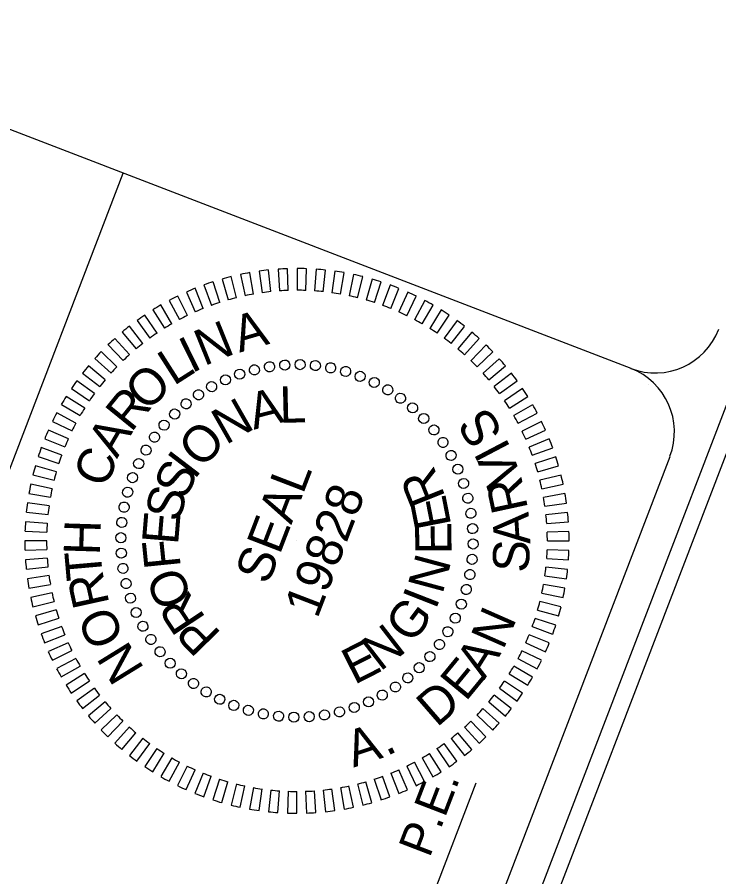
# Model space of a CAD drawing. Extents: x 1015221 to 1064345, y 619216 to 647967.
# Drawn here: x 1026680 to 1027505, y 642855 to 643866 of the extents above; entities that cross this region are included whole.
import ezdxf

# ---------------------------------------------------------------- set-up
doc = ezdxf.new("R2010")
doc.units = 0
for name, color, linetype in [('Scratch_Level_0', 7, 'Continuous'), ('Sheet PE Seal Cell', 7, 'Continuous'), ('Sheet Plot Border Inside CELL', 7, 'Continuous'), ('Sheet Title CELL', 7, 'Continuous')]:
    doc.layers.add(name, color=color, linetype=linetype)

msp = doc.modelspace()

# ---------------------------------------------------------------- linework, layer by layer
at = {"layer": 'Scratch_Level_0'}
for p, q in [((1027422.6, 643434.5), (1027422.6, 643434.5)), ((1027008.9, 643250.4), (1027008.9, 643250.4))]:
    msp.add_line(p, q, dxfattribs=at)
at = {"layer": 'Sheet PE Seal Cell'}
for p, q in [((1026964.4, 643567.5), (1026968, 643542.1)), ((1026978.2, 643543.4), (1026975.5, 643568.8)), ((1026986.7, 643569.8), (1026988.4, 643544.3)), ((1026998.7, 643544.8), (1026997.8, 643570.4)), ((1027009, 643570.6), (1027009, 643545)), ((1027019.3, 643544.8), (1027020.2, 643570.4)), ((1027031.3, 643569.8), (1027029.5, 643544.2)), ((1027039.8, 643543.3), (1027042.5, 643568.8)), ((1027053.6, 643567.4), (1027050, 643542.1)), ((1026920.7, 643558.2), (1026927.8, 643533.6)), ((1026937.7, 643536.2), (1026931.5, 643561.1)), ((1026942.4, 643563.6), (1026947.8, 643538.5)), ((1026957.8, 643540.5), (1026953.4, 643565.7)), ((1027060.1, 643540.5), (1027064.6, 643565.7)), ((1027075.6, 643563.6), (1027070.2, 643538.5)), ((1027080.3, 643536.2), (1027086.5, 643561)), ((1027097.2, 643558.1), (1027090.2, 643533.5)), ((1026898.6, 643523.5), (1026889.1, 643547.3)), ((1026899.5, 643551.3), (1026908.2, 643527.2)), ((1026918, 643530.6), (1026910.1, 643554.9)), ((1027100, 643530.5), (1027107.9, 643554.9)), ((1027118.5, 643551.2), (1027109.7, 643527.2)), ((1027119.3, 643523.5), (1027128.9, 643547.2)), ((1026879.9, 643515.2), (1026868.6, 643538.2)), ((1026878.8, 643542.9), (1026889.2, 643519.5)), ((1027139.2, 643542.9), (1027128.8, 643519.5)), ((1027138.1, 643515.1), (1027149.3, 643538.1)), ((1026861.7, 643505.5), (1026848.9, 643527.7)), ((1026858.7, 643533.1), (1026870.7, 643510.5)), ((1027159.3, 643533.1), (1027147.3, 643510.4)), ((1027156.3, 643505.5), (1027169.1, 643527.6)), ((1026839.3, 643522), (1026852.9, 643500.3)), ((1027178.7, 643521.9), (1027165.1, 643500.2)), ((1026820.8, 643509.5), (1026835.8, 643488.8)), ((1026844.3, 643494.7), (1026829.9, 643515.9)), ((1027173.7, 643494.6), (1027188, 643515.8)), ((1027197.2, 643509.4), (1027182.1, 643488.7)), ((1026827.6, 643482.6), (1026811.9, 643502.8)), ((1027190.3, 643482.5), (1027206.1, 643502.6)), ((1026811.9, 643469.4), (1026794.7, 643488.4)), ((1026803.2, 643495.7), (1026819.6, 643476.1)), ((1027214.8, 643495.6), (1027198.3, 643476)), ((1027206.1, 643469.2), (1027223.2, 643488.3)), ((1026786.6, 643480.8), (1026804.4, 643462.4)), ((1027231.4, 643480.7), (1027213.6, 643462.2)), ((1026797.1, 643455.1), (1026778.7, 643472.9)), ((1027220.9, 643455), (1027239.3, 643472.7)), ((1026783.3, 643439.8), (1026763.7, 643456.3)), ((1026771, 643464.7), (1026790.1, 643447.6)), ((1026976.6, 643455.4), (1026976.6, 643455.4)), ((1026994.6, 643457.3), (1026994.6, 643457.3)), ((1027012.5, 643457.9), (1027012.5, 643457.9)), ((1027030.6, 643456.7), (1027030.6, 643456.7)), ((1027246.9, 643464.6), (1027227.9, 643447.4)), ((1027234.6, 643439.7), (1027254.2, 643456.1)), ((1026756.7, 643447.6), (1026776.8, 643431.8)), ((1026941.4, 643446.7), (1026941.4, 643446.7)), ((1026958.7, 643451.6), (1026958.7, 643451.6)), ((1027048.6, 643453.8), (1027048.6, 643453.8)), ((1027066, 643449.7), (1027066, 643449.7)), ((1027261.3, 643447.4), (1027241.1, 643431.7)), ((1026770.7, 643423.6), (1026749.9, 643438.7)), ((1026924.6, 643439.9), (1026924.6, 643439.9)), ((1027083.3, 643444), (1027083.3, 643444)), ((1027100, 643436.7), (1027100, 643436.7)), ((1027247.3, 643423.5), (1027268, 643438.5)), ((1026743.5, 643429.5), (1026764.8, 643415.2)), ((1026908.3, 643432), (1026908.3, 643432)), ((1027115.7, 643428), (1027115.7, 643428)), ((1027274.4, 643429.4), (1027253.2, 643415)), ((1026759.2, 643406.6), (1026737.4, 643420.2)), ((1026893.1, 643422.4), (1026893.1, 643422.4)), ((1027130.9, 643418.2), (1027130.9, 643418.2)), ((1027258.8, 643406.4), (1027280.5, 643420)), ((1026731.7, 643410.6), (1026753.9, 643397.8)), ((1026878.3, 643411.7), (1026878.3, 643411.7)), ((1027145.2, 643406.9), (1027145.2, 643406.9)), ((1027286.2, 643410.4), (1027264, 643397.6)), ((1026748.9, 643388.8), (1026726.3, 643400.8)), ((1026864.9, 643399.6), (1026864.9, 643399.6)), ((1027269, 643388.6), (1027291.6, 643400.6)), ((1026721.2, 643390.8), (1026744.2, 643379.6)), ((1026852.4, 643386.7), (1026852.4, 643386.7)), ((1027158.1, 643394.5), (1027158.1, 643394.5)), ((1027296.7, 643390.7), (1027273.7, 643379.5)), ((1026739.9, 643370.3), (1026716.5, 643380.7)), ((1027170.2, 643381), (1027170.2, 643381)), ((1027278, 643370.1), (1027301.4, 643380.5)), ((1026712.1, 643370.4), (1026735.8, 643360.8)), ((1026841.1, 643372.4), (1026841.1, 643372.4)), ((1027180.9, 643366.2), (1027180.9, 643366.2)), ((1027305.8, 643370.3), (1027282, 643360.7)), ((1026732.1, 643351.2), (1026708.1, 643360)), ((1026831.3, 643357.2), (1026831.3, 643357.2)), ((1027285.7, 643351.1), (1027309.8, 643359.8)), ((1026704.4, 643349.4), (1026728.8, 643341.5)), ((1027190.5, 643351), (1027190.5, 643351)), ((1027313.4, 643349.3), (1027289.1, 643341.3)), ((1026725.8, 643331.7), (1026701.2, 643338.7)), ((1026822.6, 643341.5), (1026822.6, 643341.5)), ((1027198.4, 643334.7), (1027198.4, 643334.7)), ((1027292.1, 643331.5), (1027316.7, 643338.6)), ((1026698.3, 643328), (1026723.1, 643321.8)), ((1026815.3, 643324.8), (1026815.3, 643324.8)), ((1027319.6, 643327.8), (1027294.7, 643321.6)), ((1026720.8, 643311.7), (1026695.8, 643317.1)), ((1027205.2, 643317.9), (1027205.2, 643317.9)), ((1027297, 643311.6), (1027322.1, 643316.9)), ((1026693.6, 643306.1), (1026718.8, 643301.6)), ((1026809.6, 643307.5), (1026809.6, 643307.5)), ((1027324.2, 643305.9), (1027299, 643301.5)), ((1026717.2, 643291.5), (1026691.9, 643295.1)), ((1027210.1, 643300.6), (1027210.1, 643300.6)), ((1027300.6, 643291.3), (1027326, 643294.9)), ((1026690.5, 643284), (1026716, 643281.3)), ((1026805.5, 643290.1), (1026805.5, 643290.1)), ((1027327.3, 643283.8), (1027301.9, 643281.1)), ((1027213.9, 643282.8), (1027213.9, 643282.8)), ((1026715.1, 643271), (1026689.5, 643272.8)), ((1026802.6, 643272.1), (1026802.6, 643272.1)), ((1027215.8, 643264.7), (1027215.8, 643264.7)), ((1027302.8, 643270.9), (1027328.3, 643272.6)), ((1026688.9, 643261.7), (1026714.5, 643260.8)), ((1026801.4, 643254), (1026801.4, 643254)), ((1027328.9, 643261.5), (1027303.3, 643260.6)), ((1026714.4, 643250.5), (1026688.7, 643250.5)), ((1027216.4, 643246.8), (1027216.4, 643246.8)), ((1027303.5, 643250.3), (1027329.1, 643250.3)), ((1026688.9, 643239.3), (1026714.5, 643240.2)), ((1026802, 643236.1), (1026802, 643236.1)), ((1027328.9, 643239.1), (1027303.3, 643240)), ((1026715.1, 643229.9), (1026689.5, 643228.2)), ((1027215.2, 643228.7), (1027215.2, 643228.7)), ((1027302.7, 643229.8), (1027328.3, 643228)), ((1026690.5, 643217), (1026716, 643219.7)), ((1026804, 643218.1), (1026804, 643218.1)), ((1027327.3, 643216.8), (1027301.8, 643219.5)), ((1026717.2, 643209.5), (1026691.8, 643205.9)), ((1027212.3, 643210.8), (1027212.3, 643210.8)), ((1027300.6, 643209.3), (1027325.9, 643205.8)), ((1026693.6, 643194.9), (1026718.8, 643199.3)), ((1026807.7, 643200.2), (1026807.7, 643200.2)), ((1027208.2, 643193.3), (1027208.2, 643193.3)), ((1027324.2, 643194.7), (1027299, 643199.2)), ((1026720.8, 643189.3), (1026695.7, 643183.9)), ((1026812.6, 643182.9), (1026812.6, 643182.9)), ((1027297, 643189.1), (1027322.1, 643183.7)), ((1026698.2, 643173), (1026723.1, 643179.2)), ((1027202.5, 643176), (1027202.5, 643176)), ((1027319.5, 643172.9), (1027294.7, 643179.1)), ((1026725.7, 643169.3), (1026701.1, 643162.2)), ((1026819.4, 643166.1), (1026819.4, 643166.1)), ((1027292, 643169.1), (1027316.6, 643162.1)), ((1026704.4, 643151.6), (1026728.7, 643159.5)), ((1027195.2, 643159.4), (1027195.2, 643159.4)), ((1027313.4, 643151.4), (1027289, 643159.3)), ((1026732.1, 643149.7), (1026708, 643141)), ((1026827.3, 643149.8), (1026827.3, 643149.8)), ((1027186.5, 643143.7), (1027186.5, 643143.7)), ((1027285.7, 643149.6), (1027309.7, 643140.8)), ((1026712, 643130.6), (1026735.8, 643140.1)), ((1026836.9, 643134.6), (1026836.9, 643134.6)), ((1027305.7, 643130.4), (1027282, 643140)), ((1026739.8, 643130.7), (1026716.4, 643120.3)), ((1027176.7, 643128.4), (1027176.7, 643128.4)), ((1027278, 643130.5), (1027301.4, 643120.1)), ((1026721.1, 643110.1), (1026744.1, 643121.4)), ((1026748.8, 643112.2), (1026726.2, 643100.2)), ((1026847.7, 643119.8), (1026847.7, 643119.8)), ((1027165.4, 643114.1), (1027165.4, 643114.1)), ((1027268.9, 643112), (1027291.6, 643100)), ((1027296.6, 643110), (1027273.6, 643121.2)), ((1026731.6, 643090.4), (1026753.8, 643103.2)), ((1026859.7, 643106.4), (1026859.7, 643106.4)), ((1027286.1, 643090.2), (1027264, 643103.1)), ((1026759.1, 643094.4), (1026737.3, 643080.8)), ((1026872.6, 643093.9), (1026872.6, 643093.9)), ((1027153, 643101.2), (1027153, 643101.2)), ((1027258.7, 643094.2), (1027280.4, 643080.7)), ((1026743.4, 643071.5), (1026764.7, 643085.8)), ((1026886.9, 643082.6), (1026886.9, 643082.6)), ((1027139.5, 643089.2), (1027139.5, 643089.2)), ((1027274.3, 643071.3), (1027253.1, 643085.6)), ((1026770.6, 643077.3), (1026749.8, 643062.3)), ((1026902.2, 643072.8), (1026902.2, 643072.8)), ((1027124.7, 643078.4), (1027124.7, 643078.4)), ((1027247.2, 643077.2), (1027267.9, 643062.1)), ((1026756.6, 643053.4), (1026776.7, 643069.1)), ((1026917.9, 643064.1), (1026917.9, 643064.1)), ((1027109.5, 643068.8), (1027109.5, 643068.8)), ((1027261.1, 643053.2), (1027241, 643069)), ((1026783.2, 643061.1), (1026763.6, 643044.7)), ((1026770.9, 643036.2), (1026790, 643053.4)), ((1026934.5, 643056.8), (1026934.5, 643056.8)), ((1027076.4, 643054.1), (1027076.4, 643054.1)), ((1027093.2, 643060.9), (1027093.2, 643060.9)), ((1027246.8, 643036.1), (1027227.7, 643053.2)), ((1027234.5, 643061), (1027254.1, 643044.5)), ((1026797, 643045.9), (1026778.5, 643028.1)), ((1026951.8, 643051.1), (1026951.8, 643051.1)), ((1026969.3, 643047), (1026969.3, 643047)), ((1026987.2, 643044.1), (1026987.2, 643044.1)), ((1027005.3, 643042.9), (1027005.3, 643042.9)), ((1027023.2, 643043.5), (1027023.2, 643043.5)), ((1027041.3, 643045.5), (1027041.3, 643045.5)), ((1027059.1, 643049.2), (1027059.1, 643049.2)), ((1027220.7, 643045.7), (1027239.2, 643027.9)), ((1026786.4, 643020.2), (1026804.2, 643038.6)), ((1026811.7, 643031.6), (1026794.6, 643012.5)), ((1027205.9, 643031.5), (1027223.1, 643012.4)), ((1027231.2, 643020), (1027213.5, 643038.5)), ((1026803, 643005.2), (1026819.5, 643024.8)), ((1027214.6, 643005.1), (1027198.2, 643024.7)), ((1026827.5, 643018.3), (1026811.7, 642998.2)), ((1026820.6, 642991.4), (1026835.7, 643012.2)), ((1027197, 642991.3), (1027182, 643012.1)), ((1027190.2, 643018.2), (1027205.9, 642998.1)), ((1026844.1, 643006.3), (1026829.8, 642985)), ((1026839.2, 642978.9), (1026852.7, 643000.7)), ((1027173.5, 643006.2), (1027187.9, 642984.9)), ((1026861.6, 642995.4), (1026848.7, 642973.2)), ((1027156.1, 642995.3), (1027168.9, 642973.1)), ((1027178.5, 642978.8), (1027164.9, 643000.6)), ((1026858.5, 642967.8), (1026870.5, 642990.4)), ((1026879.7, 642985.7), (1026868.5, 642962.7)), ((1026878.6, 642958), (1026889, 642981.4)), ((1027139, 642957.9), (1027128.6, 642981.3)), ((1027138, 642985.6), (1027149.2, 642962.6)), ((1027159.1, 642967.7), (1027147.1, 642990.3)), ((1026898.5, 642977.3), (1026888.9, 642953.6)), ((1026899.3, 642949.6), (1026908.1, 642973.6)), ((1026917.8, 642970.3), (1026909.9, 642945.9)), ((1027118.3, 642949.5), (1027109.6, 642973.6)), ((1027119.2, 642977.3), (1027128.8, 642953.5)), ((1026920.6, 642942.7), (1026927.6, 642967.3)), ((1026937.6, 642964.6), (1026931.4, 642939.8)), ((1026942.2, 642937.3), (1026947.6, 642962.3)), ((1026957.7, 642960.3), (1026953.2, 642935.1)), ((1027060, 642960.3), (1027064.4, 642935.1)), ((1027075.4, 642937.2), (1027070.1, 642962.3)), ((1027080.1, 642964.6), (1027086.3, 642939.7)), ((1027097.1, 642942.6), (1027090, 642967.2)), ((1027099.8, 642970.2), (1027107.8, 642945.9)), ((1026964.3, 642933.4), (1026967.8, 642958.7)), ((1026978, 642957.5), (1026975.3, 642932)), ((1026986.5, 642931), (1026988.3, 642956.6)), ((1026998.5, 642956), (1026997.6, 642930.4)), ((1027008.8, 642930.2), (1027008.8, 642955.9)), ((1027019.1, 642956), (1027020, 642930.4)), ((1027031.1, 642931), (1027029.4, 642956.6)), ((1027039.6, 642957.5), (1027042.3, 642932)), ((1027053.4, 642933.3), (1027049.8, 642958.7))]:
    msp.add_line(p, q, dxfattribs=at)
for radius, start, end in [(320.2, 95.983, 97.983), (320.2, 91.983, 93.983), (320.2, 87.983, 89.983), (320.2, 83.983, 85.983), (320.2, 79.983, 81.983), (320.2, 103.983, 105.983), (320.2, 99.983, 101.983), (320.2, 75.983, 77.983), (320.2, 71.983, 73.983), (320.2, 111.983, 113.983), (320.2, 107.983, 109.983), (320.2, 67.983, 69.983), (320.2, 115.983, 117.983), (294.6, 103.983, 105.983), (294.6, 99.983, 101.983), (294.6, 95.983, 97.983), (294.6, 91.983, 93.983), (294.6, 87.983, 89.983), (294.6, 83.983, 85.983), (294.6, 79.983, 81.983), (294.6, 75.983, 77.983), (320.2, 63.983, 65.983), (320.2, 119.983, 121.983), (294.6, 107.983, 109.983), (294.6, 71.983, 73.983), (294.6, 67.983, 69.983), (320.2, 59.983, 61.983), (294.6, 111.983, 113.983), (294.6, 63.983, 65.983), (320.2, 55.983, 57.983), (320.2, 123.983, 125.983), (294.6, 115.983, 117.983), (294.6, 59.983, 61.983), (320.2, 51.983, 53.983), (320.2, 127.983, 129.983), (294.6, 119.983, 121.983), (294.6, 55.983, 57.983), (320.2, 131.983, 133.983), (294.6, 123.983, 125.983), (294.6, 51.983, 53.983), (320.2, 47.983, 49.983), (294.6, 127.983, 129.983), (294.6, 47.983, 49.983), (320.2, 43.983, 45.983), (320.2, 135.983, 137.983), (294.6, 131.983, 133.983), (320.2, 139.983, 141.983), (294.6, 43.983, 45.983), (320.2, 39.983, 41.983), (294.6, 135.983, 137.983), (294.6, 39.983, 41.983), (320.2, 35.983, 37.983), (320.2, 143.983, 145.983), (294.6, 139.983, 141.983), (294.6, 35.983, 37.983), (320.2, 31.983, 33.983), (320.2, 147.983, 149.983), (294.6, 143.983, 145.983), (294.6, 31.983, 33.983), (294.6, 147.983, 149.983), (320.2, 27.983, 29.983), (320.2, 151.983, 153.983), (294.6, 27.983, 29.983), (294.6, 151.983, 153.983), (320.2, 23.983, 25.983), (320.2, 155.983, 157.983), (294.6, 23.983, 25.983), (294.6, 155.983, 157.983), (320.2, 19.983, 21.983), (320.2, 159.983, 161.983), (294.6, 19.983, 21.983), (294.6, 159.983, 161.983), (320.2, 15.983, 17.983), (320.2, 163.983, 165.983), (294.6, 15.983, 17.983), (294.6, 163.983, 165.983), (320.2, 11.983, 13.983), (320.2, 167.983, 169.983), (294.6, 11.983, 13.983), (294.6, 167.983, 169.983), (320.2, 7.983, 9.983), (320.2, 171.983, 173.983), (294.6, 7.983, 9.983), (294.6, 171.983, 173.983), (320.2, 3.983, 5.983), (294.6, 3.983, 5.983), (320.2, 175.983, 177.983), (294.6, 175.983, 177.983), (294.6, 359.983, 1.983), (320.2, 359.983, 1.983), (320.2, 179.983, 181.983), (294.6, 179.983, 181.983), (294.6, 355.983, 357.983), (320.2, 355.983, 357.983), (320.2, 183.983, 185.983), (294.6, 183.983, 185.983), (294.6, 351.983, 353.983), (320.2, 351.983, 353.983), (320.2, 187.983, 189.983), (294.6, 187.983, 189.983), (294.6, 347.983, 349.983), (320.2, 347.983, 349.983), (320.2, 191.983, 193.983), (294.6, 191.983, 193.983), (294.6, 343.983, 345.983), (320.2, 343.983, 345.983), (294.6, 195.983, 197.983), (320.2, 195.983, 197.983), (294.6, 339.983, 341.983), (294.6, 199.983, 201.983), (320.2, 339.983, 341.983), (320.2, 199.983, 201.983), (294.6, 335.983, 337.983), (294.6, 203.983, 205.983), (320.2, 335.983, 337.983), (320.2, 203.983, 205.983), (294.6, 207.983, 209.983), (294.6, 331.983, 333.983), (294.6, 327.983, 329.983), (320.2, 331.983, 333.983), (320.2, 207.983, 209.983), (294.6, 211.983, 213.983), (294.6, 323.983, 325.983), (320.2, 327.983, 329.983), (320.2, 211.983, 213.983), (294.6, 215.983, 217.983), (320.2, 215.983, 217.983), (294.6, 319.983, 321.983), (320.2, 323.983, 325.983), (294.6, 219.983, 221.983), (294.6, 315.983, 317.983), (320.2, 319.983, 321.983), (320.2, 219.983, 221.983), (294.6, 223.983, 225.983), (294.6, 227.983, 229.983), (294.6, 311.983, 313.983), (320.2, 315.983, 317.983), (320.2, 223.983, 225.983), (294.6, 307.983, 309.983), (320.2, 227.983, 229.983), (294.6, 231.983, 233.983), (294.6, 303.983, 305.983), (320.2, 311.983, 313.983), (294.6, 235.983, 237.983), (320.2, 307.983, 309.983), (320.2, 231.983, 233.983), (294.6, 239.983, 241.983), (294.6, 299.983, 301.983), (320.2, 303.983, 305.983), (320.2, 235.983, 237.983), (294.6, 243.983, 245.983), (294.6, 291.983, 293.983), (294.6, 295.983, 297.983), (320.2, 239.983, 241.983), (294.6, 247.983, 249.983), (294.6, 251.983, 253.983), (294.6, 287.983, 289.983), (320.2, 299.983, 301.983), (320.2, 243.983, 245.983), (294.6, 255.983, 257.983), (294.6, 259.983, 261.983), (294.6, 279.983, 281.983), (294.6, 283.983, 285.983), (320.2, 295.983, 297.983), (320.2, 247.983, 249.983), (294.6, 263.983, 265.983), (294.6, 267.983, 269.983), (294.6, 271.983, 273.983), (294.6, 275.983, 277.983), (320.2, 291.983, 293.983), (320.2, 251.983, 253.983), (320.2, 283.983, 285.983), (320.2, 287.983, 289.983), (320.2, 255.983, 257.983), (320.2, 259.983, 261.983), (320.2, 263.983, 265.983), (320.2, 267.983, 269.983), (320.2, 271.983, 273.983), (320.2, 275.983, 277.983), (320.2, 279.983, 281.983)]:
    msp.add_arc((1027008.9, 643250.4), radius, start, end, dxfattribs=at)
for centre, major_axis in [((1026958.8, 643451.5), (-1.44, 5.77)), ((1026976.6, 643455.1), (-0.93, 5.88)), ((1026994.5, 643457.1), (-0.41, 5.93)), ((1027012.6, 643457.6), (0.11, 5.95)), ((1027030.6, 643456.5), (0.62, 5.92)), ((1027048.5, 643453.8), (1.14, 5.84)), ((1027066.1, 643449.6), (1.64, 5.72)), ((1026924.7, 643439.7), (-2.42, 5.44)), ((1026941.5, 643446.4), (-1.94, 5.63)), ((1027083.2, 643443.8), (2.13, 5.55)), ((1026908.5, 643431.7), (-2.88, 5.2)), ((1027099.8, 643436.6), (2.61, 5.35)), ((1026893.1, 643422.2), (-3.33, 4.93)), ((1027115.7, 643428), (3.07, 5.1)), ((1026878.5, 643411.5), (-3.74, 4.62)), ((1027130.8, 643418), (3.5, 4.81)), ((1026865, 643399.5), (-4.13, 4.28)), ((1027144.9, 643406.8), (3.9, 4.49)), ((1027158, 643394.3), (4.28, 4.13)), ((1026852.6, 643386.4), (-4.49, 3.9)), ((1027170, 643380.8), (4.62, 3.74)), ((1026841.3, 643372.3), (-4.81, 3.5)), ((1027180.7, 643366.2), (4.93, 3.33)), ((1026831.3, 643357.2), (-5.1, 3.07)), ((1027190.2, 643350.8), (5.2, 2.88)), ((1026822.7, 643341.3), (-5.35, 2.61)), ((1027198.2, 643334.6), (5.44, 2.42)), ((1026815.5, 643324.7), (-5.55, 2.13)), ((1027204.9, 643317.8), (5.63, 1.94)), ((1026809.7, 643307.6), (-5.72, 1.64)), ((1027210, 643300.5), (5.77, 1.44)), ((1026805.5, 643290), (-5.84, 1.14)), ((1027213.6, 643282.8), (5.88, 0.93)), ((1026802.8, 643272.1), (-5.92, 0.62)), ((1027215.6, 643264.8), (5.93, 0.41)), ((1026801.7, 643254.1), (-5.95, 0.11)), ((1027216.1, 643246.7), (5.95, -0.11)), ((1026802.2, 643236), (-5.93, -0.41)), ((1027215, 643228.7), (5.92, -0.62)), ((1026804.2, 643218.1), (-5.88, -0.93)), ((1027212.3, 643210.8), (5.84, -1.14)), ((1026807.8, 643200.3), (-5.77, -1.44)), ((1027208.1, 643193.2), (5.72, -1.64)), ((1026813, 643183), (-5.63, -1.94)), ((1027202.3, 643176.1), (5.55, -2.13)), ((1026819.6, 643166.2), (-5.44, -2.42)), ((1027195.1, 643159.5), (5.35, -2.61)), ((1026827.6, 643150), (-5.2, -2.88)), ((1027186.5, 643143.6), (5.1, -3.07)), ((1026837.1, 643134.6), (-4.93, -3.33)), ((1027176.5, 643128.6), (4.81, -3.5)), ((1026847.8, 643120), (-4.62, -3.74)), ((1026859.8, 643106.5), (-4.28, -4.13)), ((1027165.3, 643114.4), (4.49, -3.9)), ((1027152.8, 643101.3), (4.13, -4.28)), ((1026872.9, 643094.1), (-3.9, -4.49)), ((1027139.3, 643089.3), (3.74, -4.62)), ((1026887.1, 643082.8), (-3.5, -4.81)), ((1027124.7, 643078.6), (3.33, -4.93)), ((1026902.1, 643072.8), (-3.07, -5.1)), ((1027109.3, 643069.1), (2.88, -5.2)), ((1026918, 643064.2), (-2.61, -5.35)), ((1026934.6, 643057), (-2.13, -5.55)), ((1027093.1, 643061.1), (2.42, -5.44)), ((1026951.7, 643051.2), (-1.64, -5.72)), ((1026969.3, 643047), (-1.14, -5.84)), ((1027041.3, 643045.7), (0.93, -5.88)), ((1027059, 643049.3), (1.44, -5.77)), ((1027076.3, 643054.5), (1.94, -5.63)), ((1026987.2, 643044.3), (-0.62, -5.92)), ((1027005.2, 643043.2), (-0.11, -5.95)), ((1027023.3, 643043.7), (0.41, -5.93))]:
    msp.add_ellipse(centre, major_axis=major_axis, ratio=0.999708, dxfattribs=at)
at = {"layer": 'Sheet Plot Border Inside CELL'}
msp.add_lwpolyline([(1023304.8, 632396.8), (1028086.2, 644841.8), (1020206.9, 647869.1), (1015425.5, 635424)], close=True, dxfattribs=at)
at = {"layer": 'Sheet Title CELL'}
for p, q in [((1027402.1, 643453), (1026207.2, 643912)), ((1026171.3, 642034.7), (1026804.5, 643682.6)), ((1026813.6, 641909.1), (1027219.7, 642965.8))]:
    msp.add_line(p, q, dxfattribs=at)
for points in [[(1023756.2, 633628.8), (1028002.6, 644681.1)], [(1026874.9, 641857.8), (1027448.1, 643349.6)]]:
    msp.add_lwpolyline(points, dxfattribs=at)
for centre, start, end in [((1027430.4, 643527.8), 248.983, 338.983), ((1027373, 643378.5), 338.983, 68.983)]:
    msp.add_arc(centre, 80, start, end, dxfattribs=at)

# ---------------------------------------------------------------- texts
at = {"layer": 'Sheet PE Seal Cell'}
for s, height, rotation, p in [('A', 42.7, 16.3133, (1026941.3, 643471.6)), ('N', 42.7, 22.0233, (1026899.5, 643455.6)), ('I', 42.7, 26.2153, (1026884.8, 643447)), ('L', 42.7, 32.5719, (1026863.8, 643432.1)), ('O', 42.7, 43.5551, (1026831.8, 643401.1)), ('R', 42.7, 50.9668, (1026813.8, 643377)), ('A', 42.7, 14.3166, (1026958.1, 643381)), ('L', 42.7, 1.3527, (1026988.7, 643389.1)), ('N', 42.7, 29.7678, (1026925.1, 643362.7)), ('S', 42.7, 121.8808, (1027252.4, 643377.6)), ('A', 42.7, 59.5691, (1026797.1, 643346.4)), ('O', 42.7, 46.3199, (1026896.6, 643334.2)), ('I', 42.7, 117.6887, (1027261, 643359.5)), ('C', 42.7, 68.8207, (1026784.4, 643311.1)), ('I', 42.7, 52.6374, (1026888.1, 643321.3)), ('V', 42.7, 109.6004, (1027273.9, 643322.9)), ('S', 42.7, 63.6033, (1026876.8, 643297.1)), ('R', 42.7, 111.7457, (1027184, 643302)), ('SEAL', 42.69, 68.983, (1026974.9, 643197.6)), ('R', 42.7, 102.1885, (1027281, 643288.1)), ('19828', 42.69, 68.983, (1027032.8, 643158)), ('S', 42.7, 74.5692, (1026870.3, 643271.1)), ('E', 42.7, 101.0652, (1027190.6, 643268.7)), ('A', 42.7, 93.5861, (1027283.6, 643247)), ('E', 42.7, 85.2497, (1026868.9, 643245)), ('H', 42.7, 88.2167, (1026777, 643233.1)), ('E', 42.7, 90.3848, (1027190.8, 643234.7)), ('F', 42.7, 95.8079, (1026872.3, 643219.5)), ('S', 42.7, 86.3095, (1027281, 643212.3)), ('T', 42.7, 95.0333, (1026780.7, 643205.7)), ('N', 42.7, 74.9336, (1027180, 643186.8)), ('R', 42.7, 102.445, (1026788.4, 643176.6)), ('O', 42.7, 112.36, (1026886.7, 643181.8)), ('I', 42.7, 68.616, (1027172, 643168.4)), ('R', 42.7, 123.5298, (1026902.3, 643159.5)), ('G', 42.7, 53.1649, (1027144.2, 643127.9)), ('O', 42.7, 113.4282, (1026806.5, 643136)), ('N', 42.7, 66.2638, (1027251.4, 643121.3)), ('N', 42.7, 37.7137, (1027106.7, 643096.2)), ('P', 42.7, 134.2102, (1026921, 643141.3)), ('E', 42.7, 27.0332, (1027076.4, 643080.8)), ('N', 42.7, 121.6527, (1026830, 643099.9)), ('A', 42.7, 57.6614, (1027229.4, 643086.5)), ('E', 42.7, 50.5742, (1027207.4, 643060.6)), ('D', 42.7, 41.0654, (1027173.4, 643030.4)), ('A', 42.7, 18.2751, (1027075.3, 642983.8)), ('.', 42.7, 26.8775, (1027114.4, 642996.8))]:
    msp.add_text(s, height=height, rotation=rotation, dxfattribs=at).set_placement(p)
at = {"layer": 'Sheet Title CELL'}
msp.add_text('P.E.', height=40, rotation=68.983, dxfattribs=at).set_placement((1027164.8, 642876.8))

doc.saveas('drawing.dxf')
